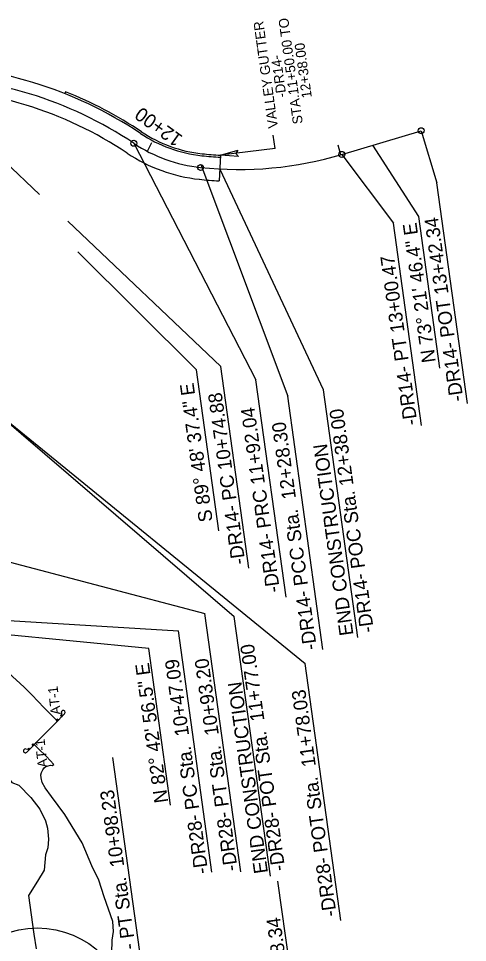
# Model space of a CAD drawing. Extents: x 472216 to 481979, y 489069 to 507339.
# Drawn here: x 478152.3 to 478379.3, y 497530.3 to 497997.1 of the extents above; entities that cross this region are included whole.
import ezdxf

# ---------------------------------------------------------------- set-up
doc = ezdxf.new("R2010")
doc.units = 0
for name, color, linetype in [('Exist Structure Minor Pipes HDPE 18 Inch', 7, 'Continuous'), ('Old_Level_12', 7, 'Continuous'), ('Prop Drainage Structure Outlet Berm Ditch 850 10 CELL', 7, 'Continuous'), ('Prop Drainage Structure Pipe CSP 15in', 7, 'Continuous'), ('Prop Drainage Structure Pipe Plug CELL', 7, 'Continuous'), ('Prop Drainage Structure Pipe RCP 24in Class III Label', 7, 'Continuous'), ('Prop Drainage Structure Tops and Inverts LABEL', 7, 'Continuous'), ('Prop Earthen Structure Head Ditch', 7, 'Continuous'), ('Sheet Block Revision CELL', 7, 'Continuous'), ('Sheet North Arrow Point CELL', 7, 'Continuous'), ('Sheet PE Seal Cell', 7, 'Continuous'), ('Sheet Plan And Profile CELL', 7, 'Continuous'), ('Sheet Plot Border Outside CELL', 7, 'Continuous'), ('Sheet Profile Grid Major CELL', 7, 'Continuous')]:
    doc.layers.add(name, color=color, linetype=linetype)

msp = doc.modelspace()

# ---------------------------------------------------------------- linework, layer by layer
at = {"layer": 'Exist Structure Minor Pipes HDPE 18 Inch'}
for centre, radius, start, end in [((478099.44, 497767.78), 207, 56.2453, 68.2889), ((478252.24, 497996.43), 68, 236.2453, 263.9435), ((478263.55, 498103.04), 175.21, 263.9435, 266.9946)]:
    msp.add_arc(centre, radius, start, end, dxfattribs=at)
at = {"layer": 'Old_Level_12'}
for p, q in [((478100.1, 497967.78), (478162.88, 497908.21)), ((478355.84, 497940.44), (478363.78, 497914.02)), ((478210.57, 497934.07), (478272.25, 497814.5)), ((478354.67, 497897.12), (478331.39, 497933.14)), ((478315.72, 497928.46), (478341.86, 497893.65)), ((478244.49, 497923.34), (478288.4, 497806.24)), ((478254, 497921.08), (478306.3, 497809.65)), ((478379.28, 497802.61), (478363.78, 497914.02)), ((478365.34, 497820.45), (478354.67, 497897.12)), ((478177.13, 497894.69), (478254.5, 497821.27)), ((478356.07, 497791.52), (478341.86, 497893.65)), ((478242.24, 497819.7), (478182.2, 497879.22)), ((478253.57, 497738.32), (478242.24, 497819.7)), ((478268.66, 497719.48), (478254.5, 497821.27)), ((478287.52, 497704.78), (478272.25, 497814.5)), ((478126.01, 497810.56), (478297.2, 497671.33)), ((478127.6, 497809.67), (478261.36, 497694.97)), ((478306.31, 497809.54), (478323.72, 497684.45)), ((478306.19, 497678.4), (478288.4, 497806.24)), ((478133.9, 497726.09), (478246.46, 497696.58)), ((478264.63, 497565.98), (478246.46, 497696.58)), ((478218.13, 497678.87), (478090.63, 497691.29)), ((478109.14, 497695.17), (478233.08, 497687.85)), ((478279.61, 497563.79), (478261.36, 497694.97)), ((478250.07, 497565.79), (478233.08, 497687.85)), ((478229.14, 497599.73), (478218.13, 497678.87)), ((478315.28, 497541.42), (478297.2, 497671.33)), ((478199.74, 497623.84), (478214.97, 497514.45)), ((478283.23, 497561.27), (478299.08, 497447.35))]:
    msp.add_line(p, q, dxfattribs=at)
for centre in [(478355.84, 497940.44), (478210.57, 497934.07), (478315.72, 497928.46), (478244.33, 497921.84)]:
    msp.add_circle(centre, 1.5, dxfattribs=at)
at = {"layer": 'Prop Drainage Structure Outlet Berm Ditch 850 10 CELL'}
msp.add_lwpolyline([(478263.48, 497927.44), (478254.37, 497928.07), (478263.21, 497930.58), (478262.22, 497928.87)], close=True, dxfattribs=at)
at = {"layer": 'Prop Drainage Structure Pipe Plug CELL'}
for p, q in [((478171.93, 497642.14), (478174.41, 497644.67)), ((478174.02, 497645.42), (478173.53, 497644.92)), ((478173.53, 497644.92), (478174.1, 497644.36)), ((478174.59, 497644.86), (478173.53, 497644.92)), ((478173.93, 497646.44), (478174.09, 497645.35)), ((478174.59, 497644.86), (478174.02, 497645.42)), ((478174.1, 497644.36), (478174.02, 497645.42)), ((478174.1, 497644.36), (478174.59, 497644.86)), ((478174.59, 497644.86), (478174.34, 497645.11)), ((478174.59, 497644.86), (478174.34, 497645.11)), ((478174.41, 497644.67), (478175.61, 497645.9)), ((478174.5, 497644.76), (478174.41, 497644.67)), ((478174.5, 497644.76), (478174.41, 497644.67)), ((478171.84, 497643.21), (478171.35, 497642.71)), ((478171.35, 497642.71), (478171.93, 497642.14)), ((478172.42, 497642.64), (478171.35, 497642.71)), ((478172.42, 497642.64), (478171.84, 497643.21)), ((478171.93, 497642.14), (478171.84, 497643.21)), ((478171.93, 497642.14), (478172.42, 497642.64)), ((478159.13, 497630.26), (478159.62, 497630.76)), ((478159.62, 497630.76), (478160.19, 497630.19)), ((478159.7, 497629.69), (478159.62, 497630.76)), ((478155.93, 497628.12), (478157.02, 497627.97)), ((478157.71, 497627.66), (478156.51, 497626.44)), ((478156.95, 497628.04), (478157.44, 497628.54)), ((478157.53, 497627.48), (478156.95, 497628.04)), ((478158.02, 497627.98), (478156.95, 497628.04)), ((478157.53, 497627.48), (478157.27, 497627.72)), ((478157.53, 497627.48), (478157.27, 497627.72)), ((478157.44, 497628.54), (478158.02, 497627.98)), ((478157.53, 497627.48), (478157.44, 497628.54)), ((478158.02, 497627.98), (478157.53, 497627.48)), ((478157.62, 497627.57), (478157.71, 497627.66)), ((478157.62, 497627.57), (478157.71, 497627.66)), ((478160.19, 497630.19), (478157.71, 497627.66)), ((478159.7, 497629.69), (478159.13, 497630.26)), ((478160.19, 497630.19), (478159.13, 497630.26)), ((478160.19, 497630.19), (478159.7, 497629.69))]:
    msp.add_line(p, q, dxfattribs=at)
for centre, major_axis, start_param, end_param in [((478174.9, 497646.59), (-0.709, 0.696), 3.141593, 7.214552), ((478155.8, 497627.14), (0.709, -0.696), 2.210226, 6.283185)]:
    msp.add_ellipse(centre, major_axis=major_axis, ratio=0.995379, start_param=start_param, end_param=end_param, dxfattribs=at)
at = {"layer": 'Prop Drainage Structure Pipe RCP 24in Class III Label'}
for p, q in [((478176.01, 497960.1), (478175.64, 497959.17)), ((478254.37, 497928.07), (478253.68, 497915.09))]:
    msp.add_line(p, q, dxfattribs=at)
for centre, radius, start, end in [((478099.44, 497767.78), 206, 56.2453, 89.8104), ((478099.44, 497767.78), 194, 56.2453, 89.8104), ((478252.24, 497996.43), 69, 236.2453, 263.9435), ((478252.24, 497996.43), 81, 236.2453, 263.9435), ((478263.55, 498103.04), 176.21, 263.9435, 266.9946), ((478263.55, 498103.04), 188.21, 263.9435, 266.9946)]:
    msp.add_arc(centre, radius, start, end, dxfattribs=at)
at = {"layer": 'Prop Drainage Structure Tops and Inverts LABEL'}
msp.add_line((478171.93, 497642.14), (478160.27, 497630.27), dxfattribs=at)
at = {"layer": 'Prop Earthen Structure Head Ditch'}
for p, q in [((478171.93, 497642.14), (478160.27, 497630.27)), ((478160.27, 497630.27), (478166.1, 497636.21)), ((478166.1, 497636.21), (478167.35, 497637.48)), ((478170.19, 497620.25), (478166.39, 497624.26))]:
    msp.add_line(p, q, dxfattribs=at)
for points in [[(478167.35, 497637.48), (478171.92, 497642.14), (478169.87, 497644.24), (478167.82, 497646.35), (478165.49, 497648.73), (478161.85, 497652.48), (478159.42, 497655.02), (478155.17, 497659.23), (478153.05, 497661.22), (478149.2, 497664.75), (478145.27, 497668.34), (478144.91, 497668.68)], [(478126.01, 497634.41), (478135.61, 497623.71), (478141.86, 497620.68), (478148.86, 497611.15), (478152.42, 497609.85), (478158.58, 497603.6), (478163.02, 497597.72), (478166, 497591.76), (478167, 497588.13), (478167.37, 497582.54), (478167.08, 497578.21), (478165.96, 497574.54), (478165.31, 497566.92), (478161.85, 497561.27), (478157.25, 497553.99), (478159.97, 497534.58), (478161.26, 497527.2)], [(478166.39, 497624.26), (478162.27, 497628.37), (478160.27, 497630.27)], [(478199.48, 497524.91), (478199.69, 497531.57), (478200.29, 497535.86), (478200, 497540.89), (478195.54, 497553.4), (478192.97, 497561.85), (478189.33, 497569.13), (478184.48, 497580.67), (478175.67, 497594.94), (478169.03, 497604.12), (478165.76, 497608.41), (478164.3, 497611.2), (478163.68, 497613.49), (478163.6, 497614.97), (478163.88, 497616.28), (478164.6, 497617.61), (478165.33, 497618.53), (478166.13, 497619.15), (478167.29, 497619.56), (478168.52, 497619.83), (478169.29, 497619.8), (478170.19, 497620.25)]]:
    msp.add_lwpolyline(points, dxfattribs=at)
at = {"layer": 'Sheet Block Revision CELL'}
for q in [(478281.05, 497938.25), (478254.37, 497928.07)]:
    msp.add_line((478281.99, 497931.52), q, dxfattribs=at)
at = {"layer": 'Sheet North Arrow Point CELL'}
msp.add_line((478315.72, 497928.46), (478355.84, 497940.44), dxfattribs=at)
for centre, radius, start, end in [((478099.44, 497767.78), 200, 56.2453, 89.8104), ((478252.24, 497996.43), 75, 236.2453, 263.9435), ((478263.55, 498103.04), 182.21, 263.9435, 286.6371)]:
    msp.add_arc(centre, radius, start, end, dxfattribs=at)
at = {"layer": 'Sheet PE Seal Cell'}
for p, q in [((478217.41, 497930.01), (478219.73, 497934.43)), ((478315.27, 497928.32), (478313.85, 497933.12)), ((478315.27, 497928.32), (478313.85, 497933.12))]:
    msp.add_line(p, q, dxfattribs=at)
at = {"layer": 'Sheet Plot Border Outside CELL'}
msp.add_circle((478161.78, 497491.24), 46.45, dxfattribs=at)

# ---------------------------------------------------------------- texts
at = {"layer": 'Old_Level_12'}
for s, p in [('-DR14- POT 13+42.34', (478377.27, 497804.06)), ('-DR14- PT 13+00.47', (478354.02, 497792.04)), ('S 89%%d 48\' 37.4" E', (478250.48, 497743.22)), ('-DR14- PC 10+74.88', (478267.02, 497721.7)), ('-DR14- PRC 11+92.04', (478284.51, 497707.58)), ('-DR14- POC Sta. 12+38.00', (478332.03, 497687.26)), ('-DR14- PCC Sta.  12+28.30', (478303.19, 497678.53)), ('END CONSTRUCTION', (478321.63, 497685.81)), ('-DR28- POT Sta.  11+77.00', (478287.19, 497566.83)), ('-DR28- PC Sta.  10+47.09', (478248.24, 497565.43)), ('-DR28- PT Sta.  10+93.20', (478263.14, 497566.81)), ('END CONSTRUCTION', (478278.4, 497565.61)), ('-DR28- POT Sta.  11+78.03', (478313.17, 497543.81)), ('-Y7- PT Sta.  10+98.23', (478213.58, 497512.73)), ('-Y7- PC Sta.  11+68.34', (478297.82, 497447.27))]:
    msp.add_text(s, height=7, rotation=97.9227, dxfattribs=at).set_placement(p)
at = {"layer": 'Prop Drainage Structure Pipe CSP 15in'}
for s, p in [('VALLEY GUTTER', (478283.52, 497942)), ('STA.11+50.00 TO', (478296.03, 497944.12)), ('12+38.00', (478300.6, 497957.27)), ('-DR14- ', (478287.76, 497957.54))]:
    msp.add_text(s, height=5, rotation=97.9227, dxfattribs=at).set_placement(p)
at = {"layer": 'Prop Drainage Structure Pipe Plug CELL'}
for p in [(478173.66, 497645.64), (478167.09, 497618.98)]:
    msp.add_text('AT-1', height=5, rotation=96.5159, dxfattribs=at).set_placement(p)
at = {"layer": 'Sheet Plan And Profile CELL'}
for s, p in [('N 73%%d 21\' 46.4" E', (478363.24, 497823.69)), ('N 82%%d 42\' 56.5" E', (478227.98, 497601.27))]:
    msp.add_text(s, height=7, rotation=97.9227, dxfattribs=at).set_placement(p)
at = {"layer": 'Sheet Profile Grid Major CELL'}
msp.add_text('12+00', height=7, rotation=144.3105, dxfattribs=at).set_placement((478235.78, 497937.45))

doc.saveas('drawing.dxf')
